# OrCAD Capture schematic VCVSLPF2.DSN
size A
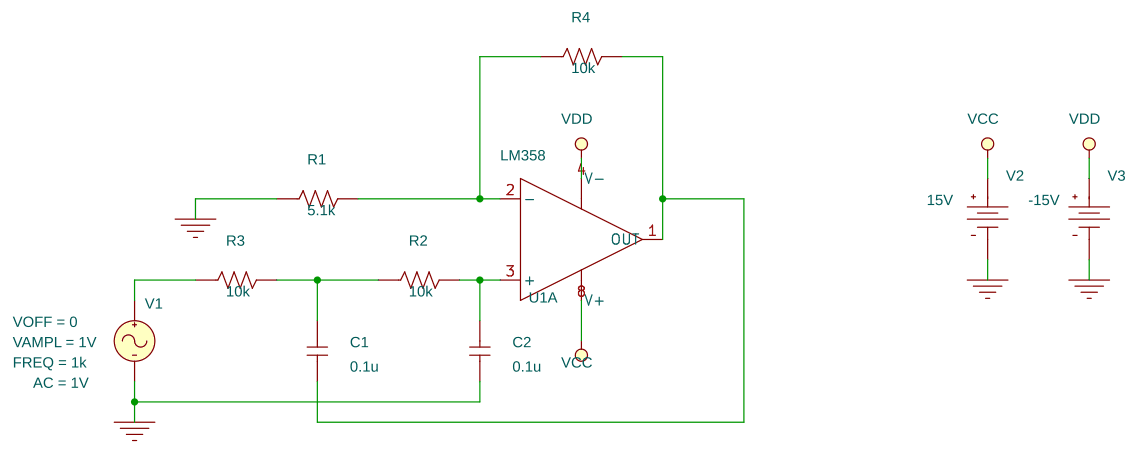
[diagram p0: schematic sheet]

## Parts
C1  0.1u  [cap196]
C2  0.1u  [cap196]
R1  5.1k  [AXRC05]
R2  10k  [AXRC05]
R3  10k  [AXRC05]
R4  10k  [AXRC05]
U1  LM358  [DIP1008W300L450]  (section A)
V1  VSIN
V2  VDC
V3  VDC

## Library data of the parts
C1 C2 = C
R1-R4 = R
U1 = LM358
V1 = VSIN: AC: 1V; FREQ: 1k; VAMPL: 1V; VOFF: 0
V2 = VDC: DC: 15V
V3 = VDC: DC: -15V

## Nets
VCC: U1.8(V+) V2.0(+)
VDD: U1.4(V-) V3.0(+)
0: C2.1 R1.1 V1.2(-) V2.1(-) V3.1(-)
N00984: R1.2 R4.1 U1.2(-)
N00994: C1.1 R4.2 U1.1(OUT)
N01218: R3.1 V1.1(+)
N01228: C1.2 R2.1 R3.2
N01242: C2.2 R2.2 U1.3(+)
